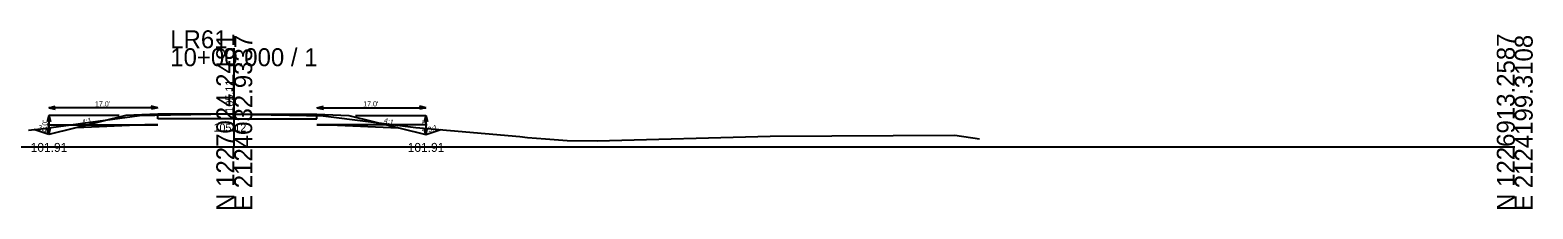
# Model space of a CAD drawing. Extents: x -26 to 1403, y -10 to 9574.
# Drawn here: x 1168.1 to 1402.8, y -9.7 to 18.2 of the extents above; entities that cross this region are included whole.
import ezdxf

# ---------------------------------------------------------------- set-up
doc = ezdxf.new("R2010")
doc.units = 0
for name, color, linetype in [('XS_CELL', 7, 'Continuous'), ('XS_P_FINISHED_GRADE', 7, 'Continuous'), ('XS_P_FINISHED_GRADE_ELEV_TX', 7, 'Continuous'), ('XS_P_SUBGRADE_GRANULAR', 7, 'Continuous'), ('XS_P_SUBGRADE_PAVEMENT', 7, 'Continuous'), ('XS_P_TX_CLEARZONE', 7, 'Continuous'), ('XS_P_TX_DCH', 7, 'Continuous'), ('XS_P_TX_FS_BS', 7, 'Continuous'), ('XS_X_GROUND', 7, 'Continuous'), ('XS_X_GROUND_TX', 7, 'Continuous')]:
    doc.layers.add(name, color=color, linetype=linetype)

msp = doc.modelspace()

# ---------------------------------------------------------------- linework, layer by layer
at = {"layer": 'XS_CELL'}
for p, q in [((1200, 0), (1200, 15.39)), ((1000, 0), (1200, 0)), ((1200, 0), (1400, 0))]:
    msp.add_line(p, q, dxfattribs=at)
at = {"layer": 'XS_P_FINISHED_GRADE'}
for p, q in [((1183.04, 4.91), (1171.04, 1.91)), ((1188.04, 5.11), (1183.04, 4.91)), ((1200, 5.11), (1188.04, 5.11)), ((1200, 5.11), (1212.92, 5.11)), ((1212.92, 5.11), (1217.92, 4.91)), ((1217.92, 4.91), (1229.92, 1.91)), ((1171.04, 1.91), (1168.69, 2.69)), ((1229.92, 1.91), (1232.26, 2.69))]:
    msp.add_line(p, q, dxfattribs=at)
at = {"layer": 'XS_P_SUBGRADE_GRANULAR'}
for p, q in [((1170.84, 3.41), (1188.04, 3.41)), ((1186.04, 3.41), (1175.32, 2.98)), ((1188.04, 3.41), (1186.04, 3.41)), ((1230.12, 3.41), (1212.92, 3.41)), ((1212.92, 3.41), (1214.92, 3.41)), ((1214.92, 3.41), (1225.64, 2.98))]:
    msp.add_line(p, q, dxfattribs=at)
at = {"layer": 'XS_P_SUBGRADE_PAVEMENT'}
for p, q in [((1188.04, 4.36), (1188.04, 5.11)), ((1212.92, 4.36), (1212.92, 5.11)), ((1200, 4.36), (1188.04, 4.36)), ((1200, 4.36), (1212.92, 4.36))]:
    msp.add_line(p, q, dxfattribs=at)
at = {"layer": 'XS_P_TX_CLEARZONE'}
for p, q in [((1171.04, 4.91), (1170.79, 3.91)), ((1171.04, 6.11), (1172.04, 6.36)), ((1171.04, 6.11), (1172.04, 5.86)), ((1188.04, 6.11), (1171.04, 6.11)), ((1171.04, 4.91), (1171.29, 3.91)), ((1171.04, 4.91), (1171.04, 1.91)), ((1182.04, 4.91), (1171.04, 4.91)), ((1188.04, 6.11), (1187.04, 6.36)), ((1188.04, 6.11), (1187.04, 5.86)), ((1212.92, 6.11), (1213.92, 6.36)), ((1212.92, 6.11), (1213.92, 5.86)), ((1212.92, 6.11), (1229.92, 6.11)), ((1218.92, 4.91), (1229.92, 4.91)), ((1229.92, 6.11), (1228.92, 6.36)), ((1229.92, 6.11), (1228.92, 5.86)), ((1229.92, 4.91), (1229.67, 3.91)), ((1229.92, 4.91), (1229.92, 1.91)), ((1229.92, 4.91), (1230.17, 3.91)), ((1171.04, 1.91), (1170.79, 2.91)), ((1171.04, 1.91), (1171.29, 2.91)), ((1229.92, 1.91), (1229.67, 2.91)), ((1229.92, 1.91), (1230.17, 2.91))]:
    msp.add_line(p, q, dxfattribs=at)
at = {"layer": 'XS_X_GROUND'}
for p, q in [((1171.39, 3.02), (1185.22, 4.9)), ((1185.22, 4.9), (1190.05, 4.98)), ((1190.05, 4.98), (1199.52, 5.13)), ((1199.52, 5.13), (1200, 5.12)), ((1200, 5.12), (1208.63, 4.93)), ((1208.63, 4.93), (1213.89, 4.82)), ((1213.89, 4.82), (1228.34, 3.04)), ((1167.86, 2.6), (1170.25, 2.86)), ((1170.25, 2.86), (1171.39, 3.02)), ((1228.34, 3.04), (1244.58, 1.59)), ((1244.58, 1.59), (1245.81, 1.46)), ((1245.81, 1.46), (1248.61, 1.26)), ((1248.61, 1.26), (1251.98, 0.97)), ((1251.98, 0.97), (1256.69, 0.95)), ((1256.69, 0.95), (1283.68, 1.69)), ((1283.68, 1.69), (1312.52, 1.81)), ((1312.52, 1.81), (1316.41, 1.26))]:
    msp.add_line(p, q, dxfattribs=at)

# ---------------------------------------------------------------- texts
at = {"layer": 'XS_CELL'}
for s, p in [('LR61', (1190, 15.39)), ('10+00.000 / 1', (1190, 12.59))]:
    msp.add_text(s, height=2.8, dxfattribs=at).set_placement(p)
for s, p in [('N 1227024.2481', (1200, -10)), ('E 2124032.9337', (1202.8, -10)), ('N 1226913.2587', (1400, -10)), ('E 2124199.3108', (1402.8, -10))]:
    msp.add_text(s, height=2.8, rotation=90, dxfattribs=at).set_placement(p)
at = {"layer": 'XS_P_FINISHED_GRADE_ELEV_TX'}
msp.add_text('105.11', height=1.25, rotation=90, dxfattribs=at).set_placement((1199.88, 5.36))
at = {"layer": 'XS_P_TX_CLEARZONE'}
for p in [(1178.25, 6.31), (1220.14, 6.31)]:
    msp.add_text("17.0'", height=0.8, dxfattribs=at).set_placement(p)
for p in [(1170.84, 2.39), (1230.12, 2.39)]:
    msp.add_text("3.0'", height=0.8, rotation=90, dxfattribs=at).set_placement(p)
at = {"layer": 'XS_P_TX_DCH'}
for p in [(1168.2, -0.79), (1227.09, -0.79)]:
    msp.add_text('101.91', height=1.4, dxfattribs=at).set_placement(p)
at = {"layer": 'XS_P_TX_FS_BS'}
for s, rotation, p in [('3:1', 341.5675, (1169.28, 2.71)), ('4:1', 14.0343, (1176.33, 3.44)), ('4:1', 345.9663, (1223.31, 3.77)), ('3:1', 18.4317, (1230.38, 2.27))]:
    msp.add_text(s, height=0.8, rotation=rotation, dxfattribs=at).set_placement(p)
at = {"layer": 'XS_X_GROUND_TX'}
msp.add_text('105.12', height=1.25, rotation=360, dxfattribs=at).set_placement((1196.76, 2.37))

doc.saveas('drawing.dxf')
